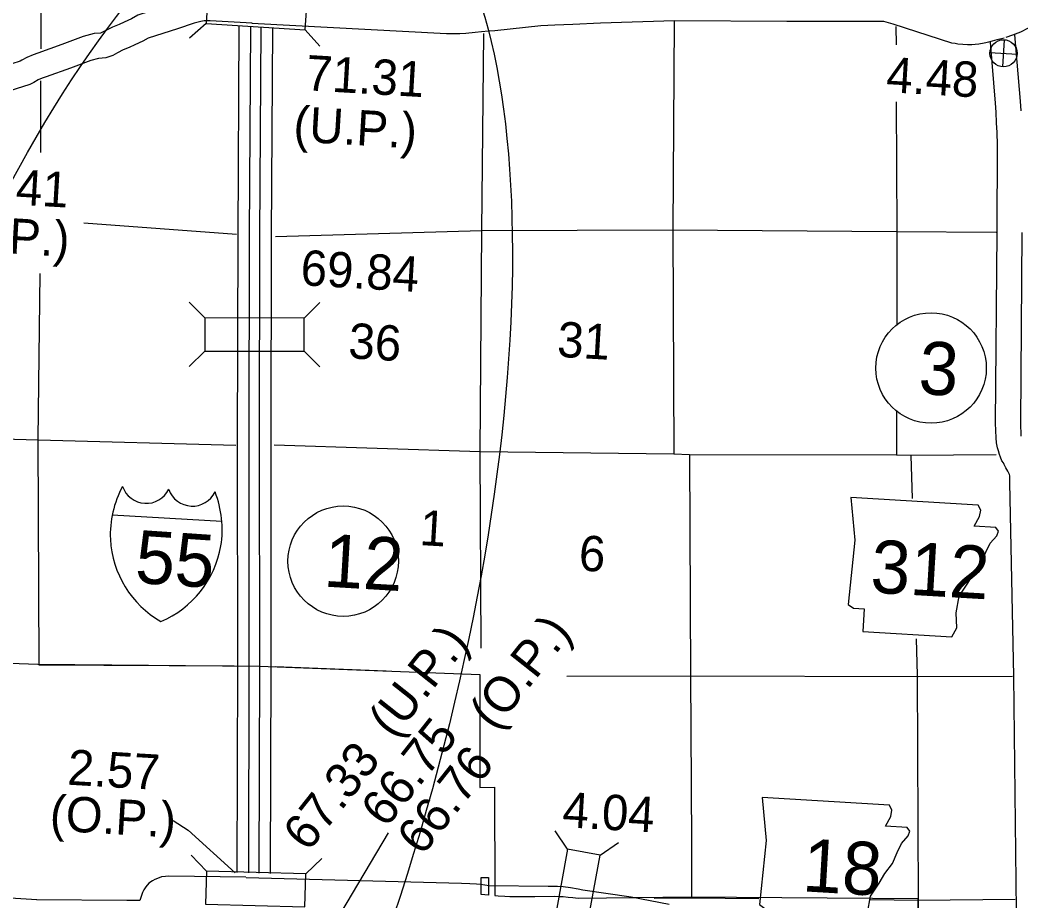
# Model space of a CAD drawing. Extents: x 1366406 to 1373462, y 376856 to 381998.
# Drawn here: x 1368242.9 to 1368436.7, y 380949 to 381119.6 of the extents above; entities that cross this region are included whole.
import ezdxf

# ---------------------------------------------------------------- set-up
doc = ezdxf.new("R2010")
doc.units = 0
for name, color, linetype in [('10', 7, 'Continuous'), ('19', 7, 'Continuous'), ('20', 7, 'Continuous'), ('21', 7, 'Continuous'), ('23', 7, 'Continuous'), ('25', 7, 'Continuous'), ('26', 7, 'Continuous'), ('27', 7, 'Continuous'), ('4', 7, 'Continuous'), ('5', 7, 'Continuous'), ('58', 7, 'Continuous'), ('6', 7, 'Continuous'), ('Default', 7, 'Continuous')]:
    doc.layers.add(name, color=color, linetype=linetype)

msp = doc.modelspace()

# ---------------------------------------------------------------- linework, layer by layer
at = {"layer": '10'}
for points in [[(1368288.09, 381123.89), (1368279.89, 381124.32), (1368278.19, 381124.34), (1368276.88, 381124.11), (1368275.23, 381123.67), (1368271.92, 381122.56), (1368265.75, 381120.58), (1368264.51, 381119.89), (1368263.11, 381119.24), (1368262.1, 381118.76), (1368260.85, 381118.24), (1368259.56, 381117.58), (1368258.92, 381117.26), (1368258.49, 381117.1), (1368257.27, 381116.99), (1368255.13, 381116.43), (1368251.03, 381114.88), (1368246.39, 381113.22), (1368245.44, 381112.9), (1368244.25, 381112.38), (1368243.29, 381111.84), (1368242.98, 381111.68), (1368238.02, 381110.11)], [(1368433.85, 381116.28), (1368435.12, 381116.77), (1368436.66, 381117.36), (1368438.13, 381118.14), (1368439.72, 381119.09), (1368442.21, 381120.57), (1368444.23, 381121.65), (1368445.2, 381122.25), (1368445.8, 381122.49), (1368446.74, 381122.78), (1368447.74, 381123.13), (1368448.09, 381123.24), (1368449.41, 381121.42)], [(1368287.84, 381119.04), (1368279.73, 381119.46), (1368278.58, 381119.47), (1368277.92, 381119.36), (1368276.63, 381119.02), (1368273.44, 381117.94), (1368267.7, 381116.1), (1368266.71, 381115.55), (1368265.16, 381114.84), (1368264.08, 381114.32), (1368262.9, 381113.83), (1368261.77, 381113.25), (1368260.87, 381112.79), (1368259.56, 381112.31), (1368258.1, 381112.19), (1368256.61, 381111.8), (1368252.71, 381110.32), (1368247.98, 381108.62), (1368247.19, 381108.36), (1368246.42, 381108.02), (1368245.6, 381107.56), (1368244.84, 381107.17), (1368239.52, 381105.49)], [(1368287.83, 381119.04), (1368325.46, 381116.99), (1368328.05, 381117.04), (1368329.26, 381117.06), (1368331.06, 381117.25), (1368332.29, 381117.43), (1368333.64, 381117.53), (1368334.84, 381117.62), (1368343.76, 381118.56), (1368346.48, 381118.67), (1368349.96, 381118.81), (1368355.27, 381119.1), (1368369.63, 381119.51), (1368391.39, 381119.4), (1368409.68, 381119.44), (1368410.12, 381119.38), (1368410.99, 381119.17), (1368411.9, 381118.88), (1368423.24, 381115.22), (1368423.96, 381115.15), (1368424.49, 381115.05), (1368425.42, 381114.94), (1368426.32, 381114.89), (1368427.18, 381114.9), (1368427.86, 381114.93), (1368428.53, 381115.01), (1368429.56, 381115.19), (1368430.5, 381115.42), (1368431.18, 381115.63), (1368432.11, 381115.87), (1368433.48, 381116.16)], [(1368436.75, 381102.07), (1368436.6, 381103.91), (1368435.54, 381116.75)], [(1368436.05, 380930.06), (1368435.31, 380992.55), (1368434.53, 381030.07), (1368434.52, 381031.38), (1368434.47, 381031.6), (1368434.4, 381031.77), (1368434.16, 381032.29), (1368433.79, 381032.91), (1368433.46, 381033.54), (1368433.31, 381033.89), (1368433.02, 381034.29), (1368432.75, 381034.95), (1368432.52, 381035.5), (1368432.36, 381036.23), (1368432.13, 381036.78), (1368431.98, 381037.77), (1368431.9, 381038.74), (1368431.79, 381041.58), (1368432.08, 381078.51), (1368432.13, 381095.43), (1368432.08, 381097.86), (1368431.99, 381099.7), (1368431.89, 381101.76), (1368431.75, 381103.52), (1368430.79, 381115.32)], [(1368436.75, 381039.05), (1368436.65, 381041.65), (1368436.94, 381078.48)], [(1368286.66, 380953.62), (1368271.73, 380953.82), (1368271.07, 380953.78), (1368270.32, 380953.71), (1368269.51, 380953.42), (1368269.04, 380953.17), (1368268.59, 380952.95), (1368267.86, 380952.46), (1368267.28, 380951.79), (1368266.9, 380951.19), (1368266.65, 380950.66), (1368266.42, 380950.09), (1368266.29, 380949.69), (1368266.12, 380949.16), (1368266.08, 380949.15), (1368265.34, 380949.13), (1368263.6, 380949.11), (1368246.1, 380949.28)], [(1368286.69, 380953.61), (1368328.42, 380952.51), (1368330.02, 380952.44), (1368331.27, 380952.35), (1368332.04, 380952.32), (1368333.75, 380952.06), (1368345.2, 380951.91), (1368346.98, 380951.92), (1368348.06, 380951.83), (1368349.47, 380951.67), (1368350.96, 380951.4), (1368351.85, 380951.17), (1368361.24, 380949.83), (1368368.61, 380948.42)], [(1368246.19, 380949.28), (1368232.76, 380950.1)]]:
    msp.add_lwpolyline(points, dxfattribs=at)
at = {"layer": '19'}
for points in [[(1368284.96, 380954.55), (1368285.07, 380994.6), (1368285.05, 381037.46), (1368285.13, 381077.92), (1368285.37, 381118.44)], [(1368287.19, 380954.49), (1368287.3, 380994.6), (1368287.28, 381037.46), (1368287.35, 381077.91), (1368287.6, 381118.28)], [(1368289.21, 380954.43), (1368289.32, 380994.6), (1368289.3, 381037.46), (1368289.38, 381077.9), (1368289.62, 381118.15)], [(1368291.44, 380954.37), (1368291.55, 380994.59), (1368291.53, 381037.46), (1368291.61, 381077.89), (1368291.85, 381118.04)]]:
    msp.add_lwpolyline(points, dxfattribs=at)
at = {"layer": '20'}
for p, q in [((1368278.94, 381118.95), (1368275.74, 381116.12)), ((1368298.15, 381117.76), (1368300.98, 381114.56)), ((1368278.71, 381061.94), (1368275.69, 381064.97)), ((1368297.96, 381061.91), (1368300.99, 381064.93)), ((1368278.7, 381055.53), (1368275.67, 381052.51)), ((1368297.95, 381055.49), (1368300.97, 381052.46)), ((1368348.94, 380959.08), (1368346.51, 380962.6)), ((1368355.25, 380957.93), (1368358.77, 380960.36)), ((1368279.01, 380954.82), (1368276.07, 380957.92)), ((1368298.25, 380954.3), (1368301.36, 380957.24))]:
    msp.add_line(p, q, dxfattribs=at)
for points in [[(1368298.55, 381124.17), (1368279.34, 381125.35), (1368278.94, 381118.95), (1368298.15, 381117.76)], [(1368278.7, 381055.53), (1368297.95, 381055.49), (1368297.96, 381061.91), (1368278.71, 381061.94)], [(1368348.94, 380959.08), (1368345.47, 380940.15), (1368351.78, 380939), (1368355.25, 380957.93)], [(1368298.25, 380954.3), (1368279.01, 380954.82), (1368278.84, 380948.41), (1368298.08, 380947.89)]]:
    msp.add_lwpolyline(points, close=True, dxfattribs=at)
at = {"layer": '21'}
for points in [[(1368403.78, 381027.16), (1368404.53, 381018.88), (1368403.25, 381006.46), (1368404.3, 381005.72), (1368406.36, 381005.59), (1368406.1, 381001.22), (1368423.33, 381000.2), (1368424.26, 381001.93), (1368424.16, 381004.82), (1368424.76, 381008.08), (1368426.42, 381010.59), (1368427.49, 381012.45), (1368428.98, 381014.42), (1368429.93, 381016.56), (1368430.72, 381018.3), (1368432.04, 381019.73), (1368432.37, 381020.67), (1368431.86, 381021.39), (1368427.62, 381021.64), (1368428.69, 381023.5), (1368428.9, 381024.72), (1368428.39, 381025.7)], [(1368386.62, 380969.05), (1368387.37, 380960.77), (1368386.09, 380948.35), (1368387.14, 380947.6), (1368389.19, 380947.48), (1368388.94, 380943.1), (1368406.17, 380942.09), (1368407.1, 380943.82), (1368406.99, 380946.71), (1368407.6, 380949.97), (1368409.25, 380952.48), (1368410.33, 380954.34), (1368411.81, 380956.31), (1368412.76, 380958.45), (1368413.55, 380960.18), (1368414.87, 380961.62), (1368415.2, 380962.56), (1368414.7, 380963.27), (1368410.45, 380963.52), (1368411.52, 380965.38), (1368411.73, 380966.61), (1368411.22, 380967.59)]]:
    msp.add_lwpolyline(points, close=True, dxfattribs=at)
at = {"layer": '23'}
msp.add_line((1368260.79, 381023.83), (1368281.99, 381022.59), dxfattribs=at)
for centre, radius, start, end in [((1368280.33, 381019.91), 19.93, 151.8499, 182.4223), ((1368267.36, 381030.88), 4.85, 198.7754, 333.9708), ((1368276.3, 381030.35), 4.85, 199.288, 334.4835), ((1368262.13, 381020.98), 19.93, 350.8366, 21.409), ((1368279.97, 381020.1), 19.58, 183.0217, 240.0865), ((1368262.5, 381021.13), 19.58, 293.1724, 350.2372)]:
    msp.add_arc(centre, radius, start, end, dxfattribs=at)
at = {"layer": '26'}
for p, q in [((1368433.18, 381110.57), (1368433.49, 381115.82)), ((1368430.7, 381113.35), (1368435.96, 381113.04))]:
    msp.add_line(p, q, dxfattribs=at)
msp.add_circle((1368433.33, 381113.19), 2.63, dxfattribs=at)
at = {"layer": '27'}
for centre in [(1368419.3, 381052.24), (1368305.49, 381014.84)]:
    msp.add_circle(centre, 10.69, dxfattribs=at)
at = {"layer": '4'}
for points in [[(1368332.62, 381116.99), (1368332.28, 381078.89), (1368331.94, 381036.05), (1368332.11, 380997.99)], [(1368214.1, 381039.24), (1368246.43, 381038.32), (1368284.69, 381037.31)], [(1368431.93, 381035.45), (1368415.41, 381035.31), (1368412.62, 381035.36), (1368372.53, 381035.44), (1368369.47, 381035.56), (1368331.99, 381036), (1368292.11, 381037.31)]]:
    msp.add_lwpolyline(points, dxfattribs=at)
at = {"layer": '5'}
for points in [[(1368247, 381160.73), (1368246.94, 381124.57), (1368246.92, 381114.02)], [(1368369.54, 381119.33), (1368369.28, 381078.99), (1368369.47, 381035.56)], [(1368412.5, 381118.36), (1368412.51, 381114.82)], [(1368246.91, 381107.87), (1368246.88, 381093.98)], [(1368412.56, 381103.8), (1368412.65, 381078.72), (1368412.64, 381060.67)], [(1368255.28, 381080.33), (1368284.82, 381078.16)], [(1368292.37, 381077.74), (1368332.28, 381078.89)], [(1368332.28, 381078.89), (1368369.28, 381078.99), (1368412.59, 381078.67), (1368431.89, 381078.58)], [(1368246.73, 381070.55), (1368246.35, 381038.46), (1368246.58, 380994.74)], [(1368412.62, 381043.8), (1368412.62, 381035.36)], [(1368372.53, 381035.44), (1368372.74, 380992.66), (1368372.84, 380971.61), (1368372.9, 380959.89)], [(1368415.41, 381035.31), (1368415.65, 381027)], [(1368416.43, 380999.81), (1368416.63, 380992.79), (1368416.82, 380949.36), (1368416.92, 380937.23)], [(1368246.58, 380994.74), (1368284.4, 380994.55)], [(1368292.33, 380994.41), (1368313.78, 380993.58)], [(1368348.81, 380992.57), (1368372.87, 380992.63), (1368416.77, 380992.51), (1368435.06, 380992.55)], [(1368372.9, 380959.89), (1368372.95, 380949.85)], [(1368365.66, 380949.59), (1368372.9, 380949.64), (1368385.96, 380949.51)], [(1368407.6, 380949.3), (1368416.72, 380949.21), (1368435.59, 380949.39)]]:
    msp.add_lwpolyline(points, dxfattribs=at)
at = {"layer": '58'}
msp.add_line((1368314.21, 380962.2), (1368297.69, 380934.46), dxfattribs=at)
msp.add_lwpolyline([(1368272.54, 380964.6), (1368275.45, 380962.78), (1368284.59, 380954.46)], dxfattribs=at)
at = {"layer": '6'}
msp.add_lwpolyline([(1368224.62, 380995.67), (1368246.34, 380994.89), (1368289.26, 380994.53), (1368331.91, 380992.9), (1368331.91, 380992.58), (1368331.96, 380971.03), (1368334.8, 380971.09), (1368334.84, 380950.07), (1368335.52, 380950.02), (1368336.78, 380949.94), (1368337.77, 380949.92), (1368339.43, 380949.91), (1368342.59, 380949.9), (1368346.34, 380949.94), (1368347.2, 380949.93), (1368347.71, 380949.91), (1368348.08, 380949.89), (1368349.07, 380949.8), (1368349.94, 380949.7), (1368350.99, 380949.55), (1368372.88, 380949.85), (1368416.72, 380949.5), (1368417.12, 380906.63)], dxfattribs=at)
msp.add_lwpolyline([(1368332.19, 380950.3), (1368332.18, 380953.6), (1368333.6, 380953.57), (1368333.61, 380950.18)], close=True, dxfattribs=at)
at = {"layer": 'Default'}
msp.add_ellipse((1368265.23, 380986.62), major_axis=(44.98, 163.09), ratio=0.352669, dxfattribs=at)

# ---------------------------------------------------------------- texts
at = {"layer": '21'}
for s, p in [('312', (1368407.4, 381008.78)), ('18', (1368394.23, 380950.92))]:
    msp.add_text(s, height=10.264, rotation=356.6294, dxfattribs=at).set_placement(p)
at = {"layer": '23'}
msp.add_text('55', height=10.264, rotation=356.1578, dxfattribs=at).set_placement((1368265.02, 381010.66))
at = {"layer": '25'}
msp.add_text('4.48', height=6.843, rotation=356.6294, dxfattribs=at).set_placement((1368410.49, 381105.68))
at = {"layer": '27'}
for s, height, p in [('3', 10.26, (1368416.71, 381047.25)), ('3', 10.26, (1368416.71, 381047.25)), ('12', 10.264, (1368301.56, 381009.93))]:
    msp.add_text(s, height=height, rotation=356.6294, dxfattribs=at).set_placement(p)
at = {"layer": '5'}
for s, height, p in [('36', 6.843, (1368306.37, 381054.15)), ('31', 6.843, (1368346.79, 381054.43)), ('1', 6.84, (1368320.17, 381017.97)), ('6', 6.84, (1368350.97, 381013.05))]:
    msp.add_text(s, height=height, rotation=356.6294, dxfattribs=at).set_placement(p)
at = {"layer": '58'}
for s, rotation, p in [('71.31', 356.6294, (1368298.13, 381106.04)), ('(U.P.)', 356.6294, (1368295.73, 381096.13)), ('20.41', 356.6294, (1368229.28, 381084.65)), ('(O.P.)', 356.6294, (1368227.96, 381075.19)), ('69.84', 356.6294, (1368297.11, 381068.31)), ('(O.P.)', 51.6294, (1368334.82, 380981.82)), ('(U.P.)', 51.6294, (1368315.26, 380980.27)), ('66.75', 51.6294, (1368313.79, 380962.97)), ('67.33', 51.6294, (1368298.72, 380958.34)), ('66.76', 51.6294, (1368320.77, 380957.57)), ('2.57', 356.6294, (1368251.99, 380971.57)), ('(O.P.)', 356.6294, (1368248.57, 380962.71)), ('4.04', 356.6294, (1368347.8, 380963.35))]:
    msp.add_text(s, height=6.843, rotation=rotation, dxfattribs=at).set_placement(p)

doc.saveas('drawing.dxf')
